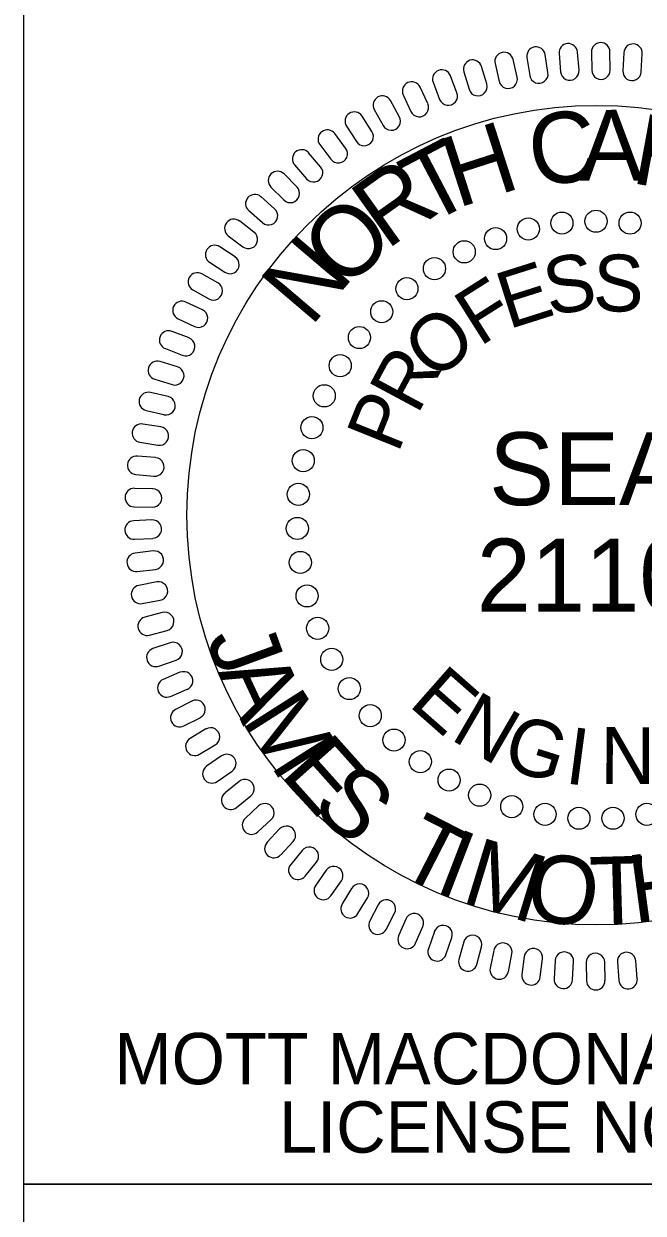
# Model space of a CAD drawing. Extents: x 1901718 to 1902220, y 193828 to 194187.
# Drawn here: x 1902112.54 to 1902117.63, y 193920.27 to 193930.05 of the extents above; entities that cross this region are included whole.
import ezdxf

# ---------------------------------------------------------------- set-up
doc = ezdxf.new("R2010")
doc.units = 0
for name, color, linetype in [('Default', 7, 'Continuous'), ('Old_Level_45', 7, 'Continuous'), ('Scratch_Level_3', 7, 'Continuous'), ('Sheet Border Standard 30in CELL', 7, 'Continuous'), ('Sheet Sticker Exception Certification CELL', 7, 'Continuous')]:
    doc.layers.add(name, color=color, linetype=linetype)

msp = doc.modelspace()

# ---------------------------------------------------------------- linework, layer by layer
at = {"layer": 'Default'}
for p, q in [((1902116.5973, 193929.6143), (1902116.564, 193929.7599)), ((1902116.6773, 193929.7761), (1902116.7007, 193929.6285)), ((1902116.8505, 193929.652), (1902116.828, 193929.7996)), ((1902116.9423, 193929.8077), (1902116.955, 193929.6588)), ((1902117.1064, 193929.6714), (1902117.0937, 193929.8213)), ((1902117.2082, 193929.8211), (1902117.2106, 193929.6711)), ((1902117.3622, 193929.6736), (1902117.3604, 193929.8236)), ((1902117.4749, 193929.8156), (1902117.4668, 193929.6665)), ((1902117.6185, 193929.6575), (1902117.6266, 193929.8076)), ((1902116.1584, 193929.6576), (1902116.201, 193929.5143)), ((1902116.3467, 193929.5587), (1902116.3039, 193929.702)), ((1902116.4159, 193929.7266), (1902116.4492, 193929.58)), ((1902115.9058, 193929.572), (1902115.9591, 193929.4319)), ((1902116.1008, 193929.4861), (1902116.0481, 193929.6263)), ((1902115.6602, 193929.4685), (1902115.7231, 193929.3322)), ((1902115.8615, 193929.3967), (1902115.798, 193929.5326)), ((1902115.4219, 193929.3481), (1902115.4946, 193929.2166)), ((1902115.6277, 193929.2902), (1902115.5556, 193929.4214)), ((1902115.4024, 193929.1684), (1902115.3214, 193929.2943)), ((1902115.4024, 193929.1684), (1902115.3214, 193929.2943)), ((1902115.186, 193929.0304), (1902115.0964, 193929.1509)), ((1902115.186, 193929.0304), (1902115.0964, 193929.1509)), ((1902115.1931, 193929.2114), (1902115.2744, 193929.0856)), ((1902115.1931, 193929.2114), (1902115.2744, 193929.0856)), ((1902114.9747, 193929.0597), (1902115.0643, 193928.9392)), ((1902114.9747, 193929.0597), (1902115.0643, 193928.9392)), ((1902114.9799, 193928.8779), (1902114.8817, 193928.9921)), ((1902114.9799, 193928.8779), (1902114.8817, 193928.9921)), ((1902114.7669, 193928.8923), (1902114.8651, 193928.7791)), ((1902114.7669, 193928.8923), (1902114.8651, 193928.7791)), ((1902114.7855, 193928.7116), (1902114.6797, 193928.818)), ((1902114.5711, 193928.7106), (1902114.677, 193928.6051)), ((1902114.602, 193928.5325), (1902114.4895, 193928.6316)), ((1902114.3894, 193928.5166), (1902114.5019, 193928.4184)), ((1902114.4317, 193928.3408), (1902114.3125, 193928.4315)), ((1902114.2211, 193928.3098), (1902114.3404, 193928.219)), ((1902114.2764, 193928.1373), (1902114.1501, 193928.2192)), ((1902114.0675, 193928.092), (1902114.1929, 193928.01)), ((1902114.1345, 193927.9237), (1902114.0037, 193927.9969)), ((1902113.9295, 193927.864), (1902114.0603, 193927.7913)), ((1902114.0079, 193927.701), (1902113.8725, 193927.7643)), ((1902113.8077, 193927.6265), (1902113.943, 193927.5631)), ((1902113.8977, 193927.4698), (1902113.7579, 193927.5238)), ((1902113.7033, 193927.3818), (1902113.8422, 193927.3278)), ((1902113.8031, 193927.2314), (1902113.6603, 193927.2752)), ((1902113.6157, 193927.1302), (1902113.7585, 193927.0855)), ((1902113.7266, 193926.9867), (1902113.5808, 193927.0206)), ((1902113.5454, 193926.8726), (1902113.6912, 193926.8388)), ((1902113.6661, 193926.7379), (1902113.518, 193926.7615)), ((1902113.4944, 193926.6112), (1902113.6423, 193926.5876)), ((1902113.6234, 193926.4853), (1902113.4748, 193926.4981)), ((1902113.4611, 193926.3473), (1902113.6097, 193926.3336)), ((1902113.5986, 193926.2298), (1902113.4495, 193926.2327)), ((1902113.4457, 193926.081), (1902113.5958, 193926.0773)), ((1902113.5918, 193925.9736), (1902113.4425, 193925.9666)), ((1902113.4499, 193925.8141), (1902113.5998, 193925.8215)), ((1902113.6032, 193925.7179), (1902113.4543, 193925.6998)), ((1902113.4722, 193925.5484), (1902113.6214, 193925.5666)), ((1902113.6319, 193925.4631), (1902113.4844, 193925.435)), ((1902113.5134, 193925.2853), (1902113.6606, 193925.3134)), ((1902113.6783, 193925.2106), (1902113.5333, 193925.1727)), ((1902113.5722, 193925.0253), (1902113.7171, 193925.0635)), ((1902113.7431, 193924.9623), (1902113.6005, 193924.9142)), ((1902113.6495, 193924.7704), (1902113.7918, 193924.8185)), ((1902113.8233, 193924.7199), (1902113.6855, 193924.6616)), ((1902113.7444, 193924.5209), (1902113.8829, 193924.5798)), ((1902113.9212, 193924.4829), (1902113.7874, 193924.4147)), ((1902113.8565, 193924.2795), (1902113.9902, 193924.3466)), ((1902114.0362, 193924.2538), (1902113.9072, 193924.1764)), ((1902113.9851, 193924.0459), (1902114.1136, 193924.1223)), ((1902114.1657, 193924.0326), (1902114.043, 193923.9467)), ((1902114.1295, 193923.8218), (1902114.2528, 193923.9074)), ((1902114.3105, 193923.8209), (1902114.1941, 193923.7273)), ((1902114.2889, 193923.6088), (1902114.4062, 193923.703)), ((1902114.4697, 193923.6202), (1902114.3605, 193923.5184)), ((1902114.4639, 193923.4073), (1902114.5731, 193923.5091)), ((1902114.6431, 193923.4311), (1902114.5407, 193923.3225)), ((1902114.6518, 193923.2178), (1902114.7541, 193923.3273)), ((1902114.8292, 193923.2548), (1902114.7347, 193923.1383)), ((1902114.8525, 193923.0423), (1902114.947, 193923.1588)), ((1902115.0267, 193923.0917), (1902114.94, 193922.9691)), ((1902115.0648, 193922.8818), (1902115.1508, 193923.0041)), ((1902115.2351, 193922.9426), (1902115.1577, 193922.8149)), ((1902115.2877, 193922.736), (1902115.365, 193922.8638)), ((1902115.4538, 193922.8082), (1902115.3852, 193922.6753)), ((1902115.5206, 193922.6058), (1902115.5892, 193922.7396)), ((1902115.6811, 193922.6903), (1902115.6218, 193922.552)), ((1902115.7617, 193922.4927), (1902115.8204, 193922.6301)), ((1902115.9159, 193922.588), (1902115.8665, 193922.446)), ((1902116.0103, 193922.3958), (1902116.0597, 193922.538)), ((1902116.1575, 193922.5021), (1902116.1181, 193922.3578)), ((1902116.2649, 193922.3177), (1902116.304, 193922.4621)), ((1902116.4043, 193922.4329), (1902116.3751, 193922.2866)), ((1902116.5246, 193922.2565), (1902116.5531, 193922.4038)), ((1902116.6555, 193922.3818), (1902116.6362, 193922.2331)), ((1902116.7874, 193922.2142), (1902116.8063, 193922.3629)), ((1902116.9095, 193922.3487), (1902116.9011, 193922.1986)), ((1902117.0528, 193922.1902), (1902117.0612, 193922.3403)), ((1902117.1649, 193922.3322), (1902117.1673, 193922.1823)), ((1902117.3198, 193922.185), (1902117.3171, 193922.335)), ((1902117.4216, 193922.3347), (1902117.4343, 193922.1854)), ((1902117.5857, 193922.1981), (1902117.5731, 193922.3473))]:
    msp.add_line(p, q, dxfattribs=at)
for centre in [(1902116.9654, 193928.4139), (1902117.2455, 193928.4299), (1902117.5262, 193928.4138), (1902116.4198, 193928.287), (1902116.689, 193928.366), (1902116.1614, 193928.1778), (1902115.9171, 193928.0398), (1902115.6901, 193927.8749), (1902115.4834, 193927.6852), (1902115.2997, 193927.4732), (1902115.1413, 193927.2416), (1902115.0104, 193926.9935), (1902114.9086, 193926.7321), (1902114.8372, 193926.4607), (1902114.7973, 193926.183), (1902114.7893, 193925.9026), (1902114.8132, 193925.6231), (1902114.8689, 193925.3481), (1902114.9556, 193925.0813), (1902115.0721, 193924.8261), (1902115.217, 193924.5858), (1902115.3883, 193924.3636), (1902115.5838, 193924.1624), (1902115.801, 193923.9848), (1902116.037, 193923.8331), (1902116.2888, 193923.7093), (1902116.553, 193923.615), (1902116.8262, 193923.5514), (1902117.105, 193923.5194), (1902117.3855, 193923.5193), (1902117.6642, 193923.5513)]:
    msp.add_circle(centre, 0.091, dxfattribs=at)
for centre, start, end in [((1902116.7525, 193929.788), 8.83494, 188.83432), ((1902117.0178, 193929.8144), 4.83494, 184.83432), ((1902117.2843, 193929.8223), 0.83494, 180.83432), ((1902117.5506, 193929.8116), 356.83494, 176.83432), ((1902116.2307, 193929.68), 16.83494, 196.83432), ((1902116.4897, 193929.7431), 12.83494, 192.83432), ((1902115.9768, 193929.599), 20.83494, 200.83432), ((1902116.7755, 193929.6399), 188.83432, 8.83494), ((1902117.0304, 193929.6651), 184.83432, 4.83494), ((1902117.2864, 193929.6724), 180.83432, 0.83494), ((1902117.5423, 193929.6619), 176.83432, 356.83494), ((1902115.729, 193929.5004), 24.83494, 204.83432), ((1902116.2741, 193929.5365), 196.83432, 16.83494), ((1902116.523, 193929.597), 192.83432, 12.83494), ((1902115.4888, 193929.3848), 28.83494, 208.83432), ((1902116.0301, 193929.4589), 200.83432, 20.83494), ((1902115.792, 193929.3644), 204.83432, 24.83494), ((1902115.2572, 193929.2528), 32.83494, 212.83432), ((1902115.2572, 193929.2528), 32.83494, 212.83432), ((1902115.5611, 193929.2535), 208.83432, 28.83494), ((1902115.0354, 193929.1049), 36.83494, 216.83432), ((1902115.0354, 193929.1049), 36.83494, 216.83432), ((1902115.3385, 193929.1268), 212.83432, 32.83494), ((1902115.3385, 193929.1268), 212.83432, 32.83494), ((1902114.8245, 193928.9419), 40.83494, 220.83432), ((1902114.8245, 193928.9419), 40.83494, 220.83432), ((1902115.1253, 193928.9849), 216.83432, 36.83494), ((1902115.1253, 193928.9849), 216.83432, 36.83494), ((1902114.9225, 193928.8285), 220.83432, 40.83494), ((1902114.9225, 193928.8285), 220.83432, 40.83494), ((1902114.6254, 193928.7646), 44.83494, 224.83432), ((1902114.7311, 193928.6583), 224.83432, 44.83494), ((1902114.4392, 193928.5738), 48.83494, 228.83432), ((1902114.5521, 193928.4751), 228.83432, 48.83494), ((1902114.2668, 193928.3705), 52.83494, 232.83432), ((1902114.3862, 193928.28), 232.83432, 52.83494), ((1902114.1089, 193928.1557), 56.83494, 236.83432), ((1902114.2344, 193928.0737), 236.83432, 56.83494), ((1902113.9665, 193927.9304), 60.83494, 240.83432), ((1902114.0973, 193927.8573), 240.83432, 60.83494), ((1902113.84, 193927.6957), 64.83494, 244.83432), ((1902113.9757, 193927.6319), 244.83432, 64.83494), ((1902113.7303, 193927.4527), 68.83494, 248.83432), ((1902113.8701, 193927.3986), 248.83432, 68.83494), ((1902113.6378, 193927.2027), 72.83494, 252.83432), ((1902113.781, 193927.1585), 252.83432, 72.83494), ((1902113.5629, 193926.9468), 76.83494, 256.83432), ((1902113.7089, 193926.9127), 256.83432, 76.83494), ((1902113.5061, 193926.6864), 80.83494, 260.83432), ((1902113.6541, 193926.6625), 260.83432, 80.83494), ((1902113.4676, 193926.4226), 84.83494, 264.83432), ((1902113.6169, 193926.4091), 264.83432, 84.83494), ((1902113.4476, 193926.1568), 88.83494, 268.83432), ((1902113.5975, 193926.1537), 268.83432, 88.83494), ((1902113.4462, 193925.8902), 92.83494, 272.83432), ((1902113.5959, 193925.8976), 272.83432, 92.83494), ((1902113.4633, 193925.6241), 96.83494, 276.83432), ((1902113.6122, 193925.642), 276.83432, 96.83494), ((1902113.499, 193925.36), 100.83494, 280.83432), ((1902113.6463, 193925.3881), 280.83432, 100.83494), ((1902113.5531, 193925.0989), 104.83494, 284.83432), ((1902113.698, 193925.1373), 284.83432, 104.83494), ((1902113.767, 193924.8906), 288.83432, 108.83494), ((1902113.6252, 193924.8423), 108.83494, 288.83432), ((1902113.715, 193924.5913), 112.83494, 292.83432), ((1902113.8532, 193924.6494), 292.83432, 112.83494), ((1902113.9559, 193924.4148), 296.83432, 116.83494), ((1902113.8221, 193924.3471), 116.83494, 296.83432), ((1902114.0747, 193924.1879), 300.83432, 120.83494), ((1902113.946, 193924.1111), 120.83494, 300.83432), ((1902114.2091, 193923.9699), 304.83432, 124.83494), ((1902114.0861, 193923.8843), 124.83494, 304.83432), ((1902114.3584, 193923.7618), 308.83432, 128.83494), ((1902114.2416, 193923.6678), 128.83494, 308.83432), ((1902114.5218, 193923.5645), 312.83432, 132.83494), ((1902114.4119, 193923.4626), 132.83494, 312.83432), ((1902114.6986, 193923.3792), 316.83432, 136.83494), ((1902114.596, 193923.2699), 136.83494, 316.83432), ((1902114.8879, 193923.2067), 320.83432, 140.83494), ((1902114.7932, 193923.0904), 140.83494, 320.83432), ((1902115.0887, 193923.0477), 324.83432, 144.83494), ((1902115.0024, 193922.9252), 144.83494, 324.83432), ((1902115.3002, 193922.9032), 328.83432, 148.83494), ((1902115.2226, 193922.7749), 148.83494, 328.83432), ((1902115.5212, 193922.7738), 332.83432, 152.83494), ((1902115.7507, 193922.6601), 336.83432, 156.83494), ((1902115.4527, 193922.6404), 152.83494, 332.83432), ((1902115.9876, 193922.5627), 340.83432, 160.83494), ((1902115.6917, 193922.5223), 156.83494, 336.83432), ((1902116.2307, 193922.482), 344.83432, 164.83494), ((1902115.9384, 193922.4211), 160.83494, 340.83432), ((1902116.4788, 193922.4185), 348.83432, 168.83494), ((1902116.7308, 193922.3725), 352.83432, 172.83494), ((1902116.9853, 193922.3442), 356.83432, 176.83494), ((1902117.2412, 193922.3337), 0.83432, 180.83494), ((1902117.4972, 193922.341), 4.83432, 184.83494), ((1902116.1915, 193922.3374), 164.83494, 344.83432), ((1902116.4498, 193922.2715), 168.83494, 348.83432), ((1902116.7121, 193922.2238), 172.83494, 352.83432), ((1902116.977, 193922.1945), 176.83494, 356.83432), ((1902117.2434, 193922.1838), 180.83494, 0.83432), ((1902117.5099, 193922.1917), 184.83494, 4.83432)]:
    msp.add_arc(centre, 0.0761, start, end, dxfattribs=at)
at = {"layer": 'Scratch_Level_3'}
msp.add_circle((1902117.2512, 193926.0122), 3.37, dxfattribs=at)
at = {"layer": 'Sheet Border Standard 30in CELL'}
msp.add_lwpolyline([(1902112.5386, 193931.7593), (1902122.5436, 193931.7593), (1902122.5436, 193920.5093), (1902112.5386, 193920.5093)], close=True, dxfattribs=at)
at = {"layer": 'Sheet Sticker Exception Certification CELL'}
for p, q in [((1902112.5386, 193918.1593), (1902112.5386, 193920.5093)), ((1902112.5386, 193920.5093), (1902132.5423, 193920.5093))]:
    msp.add_line(p, q, dxfattribs=at)

# ---------------------------------------------------------------- texts
at = {"layer": 'Default'}
for s, height, rotation, p in [('C', 0.5824, 7.97778, (1902116.7328, 193928.7081)), ('A', 0.5824, 0.19447, (1902117.1121, 193928.7624)), ('R', 0.5824, 349.6661, (1902117.5231, 193928.7472)), ('H', 0.5824, 17.84243, (1902116.104, 193928.5354)), ('T', 0.5824, 27.61162, (1902115.8564, 193928.3899)), ('R', 0.5825, 35.44084, (1902115.5224, 193928.1886)), ('O', 0.5825, 42.88363, (1902115.1731, 193927.8518)), ('N', 0.5825, 49.61241, (1902114.8987, 193927.5526)), ('E', 0.4672, 17.58975, (1902116.5252, 193927.5388)), ('S', 0.4672, 10.21722, (1902116.862, 193927.6494)), ('S', 0.4672, 359.00874, (1902117.2185, 193927.6911)), ('F', 0.4672, 32.33488, (1902116.2884, 193927.3939)), ('O', 0.4672, 40.60854, (1902115.9215, 193927.103)), ('R', 0.4672, 61.82557, (1902115.7758, 193926.8295)), ('P', 0.4672, 68.05886, (1902115.6162, 193926.5119)), ('SEAL', 0.59922, 360, (1902116.3662, 193926.0946)), ('J', 0.56, 289.96963, (1902114.0334, 193925.0001)), ('A', 0.56, 294.99089, (1902114.1343, 193924.7223)), ('E', 0.4672, 318.61005, (1902115.6954, 193924.4515)), ('M', 0.56, 302.46035, (1902114.3285, 193924.3281)), ('N', 0.4672, 329.84458, (1902116.0377, 193924.1732)), ('G', 0.4672, 342.61239, (1902116.4571, 193923.9438)), ('I', 0.4672, 352.41619, (1902116.9805, 193923.8088)), ('N', 0.4672, 359.78871, (1902117.2802, 193923.8026)), ('E', 0.56, 311.76755, (1902114.6393, 193923.8776)), ('S', 0.56, 318.0541, (1902114.8888, 193923.6044)), ('T', 0.56, 332.88741, (1902115.5839, 193923.0798)), ('I', 0.56, 338.96273, (1902115.9036, 193922.9198)), ('M', 0.56, 342.98906, (1902116.1241, 193922.8329)), ('O', 0.56, 352.29627, (1902116.6531, 193922.6924)), ('T', 0.56, 1.6246, (1902117.1991, 193922.6394)), ('H', 0.56, 7.69991, (1902117.5564, 193922.6528))]:
    msp.add_text(s, height=height, rotation=rotation, dxfattribs=at).set_placement(p)
msp.add_text('21102', height=0.5994, dxfattribs=at).set_placement((1902116.2647, 193925.2196))
at = {"layer": 'Old_Level_45'}
for s, p in [('MOTT MACDONALD I & E, LLC', (1902113.2847, 193921.3317)), (' LICENSE NO. F-0669', (1902114.4812, 193920.7692))]:
    msp.add_text(s, height=0.421875, rotation=360, dxfattribs=at).set_placement(p)

doc.saveas('drawing.dxf')
